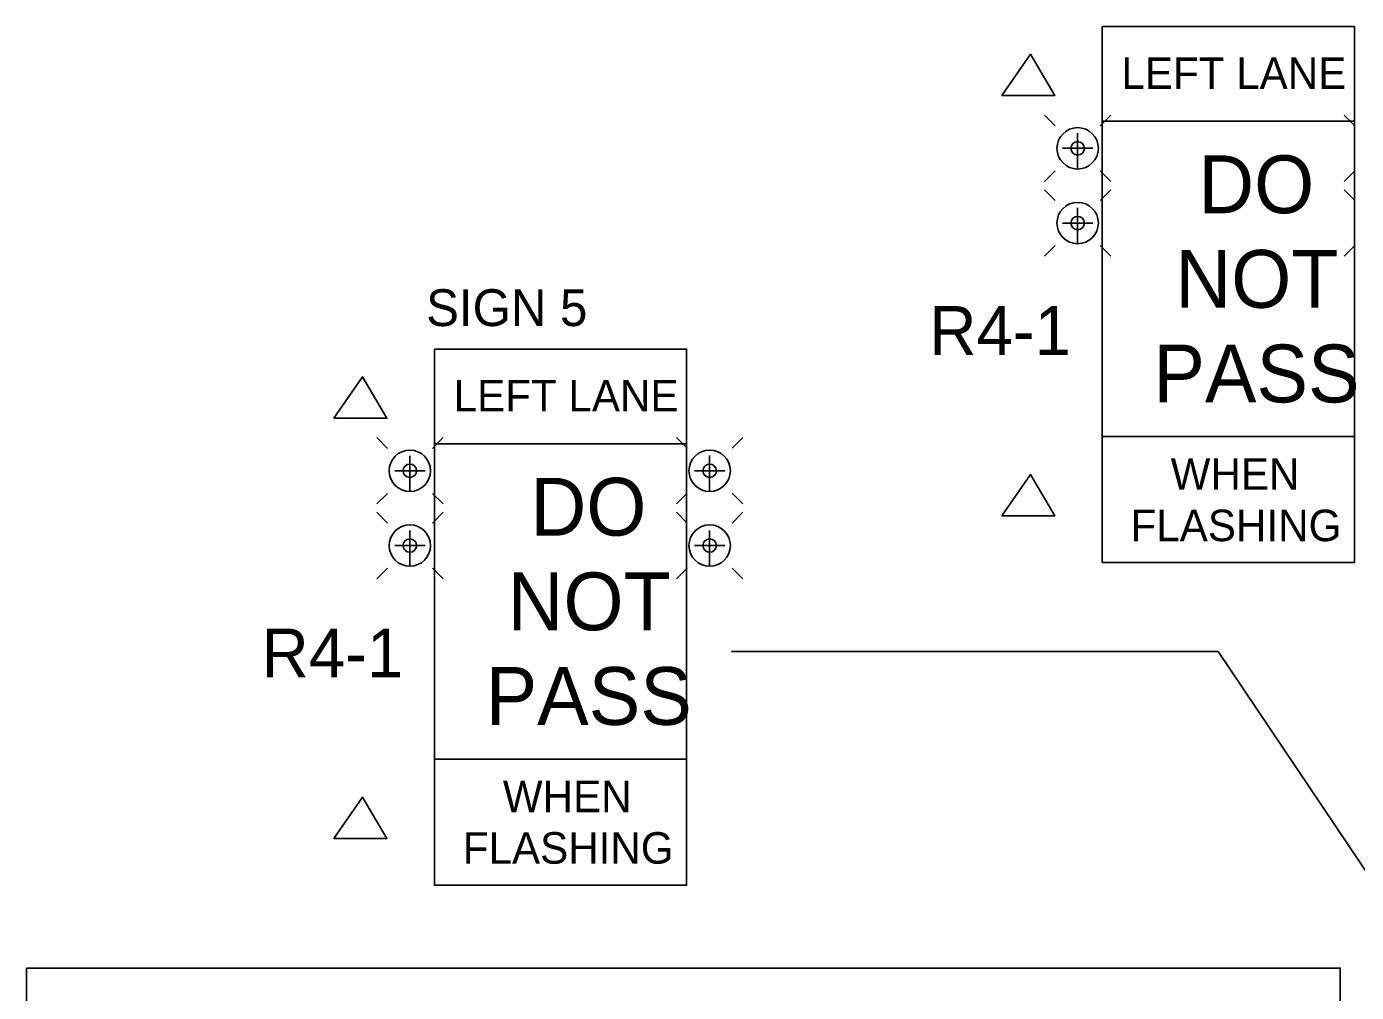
# Model space of a CAD drawing. Extents: x 15278 to 18126, y 1908 to 6555.
# Drawn here: x 16278.3 to 16480.8, y 2648.2 to 2795.2 of the extents above; entities that cross this region are included whole.
import ezdxf

# ---------------------------------------------------------------- set-up
doc = ezdxf.new("R2010")
doc.units = 0
doc.layers.add('TRAFFIC_SIGNS_PR', color=7, linetype='Continuous')
doc.layers.add('TYPICAL_TEXT_DIMEN_PR', color=7, linetype='Continuous')

msp = doc.modelspace()

# ---------------------------------------------------------------- linework, layer by layer
at = {"layer": 'TRAFFIC_SIGNS_PR'}
for p, q in [((16434.9, 2780.08), (16433.27, 2781.71)), ((16441.74, 2780.08), (16443.37, 2781.71)), ((16442.06, 2732.78), (16442.06, 2780.78)), ((16442.06, 2780.78), (16480.46, 2780.78)), ((16480.54, 2780.1), (16478.91, 2781.72)), ((16480.46, 2732.78), (16480.46, 2780.78)), ((16438.32, 2776.66), (16438.32, 2778.96)), ((16438.32, 2776.66), (16436.02, 2776.66)), ((16438.32, 2776.66), (16438.32, 2773.51)), ((16438.32, 2776.66), (16440.62, 2776.66)), ((16434.9, 2773.23), (16433.27, 2771.6)), ((16443.37, 2771.6), (16441.74, 2773.23)), ((16480.54, 2773.25), (16478.91, 2771.62)), ((16434.9, 2768.71), (16433.27, 2770.33)), ((16441.74, 2768.7), (16443.37, 2770.33)), ((16480.54, 2768.71), (16478.91, 2770.33)), ((16438.32, 2765.28), (16438.32, 2767.58)), ((16438.32, 2765.28), (16436.02, 2765.28)), ((16438.32, 2765.28), (16438.32, 2762.13)), ((16438.32, 2765.28), (16440.62, 2765.28)), ((16434.9, 2761.86), (16433.27, 2760.23)), ((16443.37, 2760.23), (16441.74, 2761.86)), ((16480.54, 2761.86), (16478.91, 2760.23)), ((16333.22, 2730.99), (16331.59, 2732.62)), ((16340.07, 2730.99), (16341.7, 2732.62)), ((16340.38, 2683.7), (16340.38, 2731.7)), ((16340.38, 2731.7), (16378.78, 2731.7)), ((16378.86, 2731.01), (16377.24, 2732.64)), ((16378.78, 2683.7), (16378.78, 2731.7)), ((16385.71, 2731.01), (16387.34, 2732.64)), ((16442.06, 2732.78), (16480.46, 2732.78)), ((16336.64, 2727.57), (16336.64, 2729.87)), ((16382.29, 2727.59), (16382.29, 2729.89)), ((16336.64, 2727.57), (16334.34, 2727.57)), ((16336.64, 2727.57), (16336.64, 2724.42)), ((16336.64, 2727.57), (16338.95, 2727.57)), ((16382.29, 2727.59), (16379.99, 2727.59)), ((16382.29, 2727.59), (16382.29, 2724.43)), ((16382.29, 2727.59), (16384.59, 2727.59)), ((16333.22, 2724.14), (16331.59, 2722.52)), ((16341.69, 2722.52), (16340.07, 2724.14)), ((16378.86, 2724.16), (16377.24, 2722.53)), ((16387.34, 2722.53), (16385.71, 2724.16)), ((16333.22, 2719.62), (16331.59, 2721.25)), ((16340.07, 2719.62), (16341.7, 2721.25)), ((16378.86, 2719.62), (16377.24, 2721.25)), ((16385.71, 2719.62), (16387.34, 2721.25)), ((16336.64, 2716.19), (16336.64, 2718.5)), ((16382.29, 2716.19), (16382.29, 2718.5)), ((16336.64, 2716.19), (16334.34, 2716.19)), ((16336.64, 2716.19), (16336.64, 2713.04)), ((16336.64, 2716.19), (16338.95, 2716.19)), ((16382.29, 2716.19), (16379.99, 2716.19)), ((16382.29, 2716.19), (16382.29, 2713.04)), ((16382.29, 2716.19), (16384.59, 2716.19)), ((16333.22, 2712.77), (16331.59, 2711.14)), ((16341.69, 2711.14), (16340.07, 2712.77)), ((16378.86, 2712.77), (16377.24, 2711.14)), ((16387.34, 2711.14), (16385.71, 2712.77)), ((16340.38, 2683.7), (16378.78, 2683.7))]:
    msp.add_line(p, q, dxfattribs=at)
msp.add_lwpolyline([(16278.29, 2651.89), (16478.29, 2651.89), (16478.29, 2547.89), (16278.29, 2547.89)], close=True, dxfattribs=at)
for centre, radius in [((16438.32, 2776.65), 3.15), ((16438.32, 2776.65), 1.02), ((16438.32, 2765.28), 3.15), ((16438.32, 2765.28), 1.02), ((16336.64, 2727.57), 3.15), ((16382.29, 2727.58), 3.15), ((16336.64, 2727.57), 1.02), ((16382.29, 2727.58), 1.02), ((16336.64, 2716.19), 3.15), ((16382.29, 2716.19), 3.15), ((16336.64, 2716.19), 1.02), ((16382.29, 2716.19), 1.02)]:
    msp.add_circle(centre, radius, dxfattribs=at)
at = {"layer": 'TYPICAL_TEXT_DIMEN_PR'}
for p, q in [((16459.72, 2700.07), (16385.59, 2700.07)), ((16494.38, 2648.48), (16459.72, 2700.07))]:
    msp.add_line(p, q, dxfattribs=at)
for points in [[(16442.06, 2795.18), (16480.46, 2795.18), (16480.46, 2780.78), (16442.06, 2780.78)], [(16426.76, 2784.67), (16431.12, 2790.97), (16434.83, 2784.67)], [(16340.38, 2746.09), (16378.78, 2746.09), (16378.78, 2731.7), (16340.38, 2731.7)], [(16325.08, 2735.58), (16329.45, 2741.88), (16333.15, 2735.58)], [(16442.06, 2732.78), (16480.46, 2732.78), (16480.46, 2713.59), (16442.06, 2713.59)], [(16426.76, 2720.7), (16431.12, 2727.01), (16434.83, 2720.7)], [(16340.38, 2683.7), (16378.78, 2683.7), (16378.78, 2664.5), (16340.38, 2664.5)], [(16325.08, 2671.62), (16329.45, 2677.92), (16333.15, 2671.62)]]:
    msp.add_lwpolyline(points, close=True, dxfattribs=at)

# ---------------------------------------------------------------- texts
at = {"layer": 'TRAFFIC_SIGNS_PR'}
for s, height, p in [('DO', 8.8, (16456.69, 2766.78)), ('NOT', 8.8, (16453.2, 2752.38)), ('R4-1', 7.44, (16415.74, 2745.2)), ('PASS', 8.8, (16449.85, 2737.98)), ('DO', 8.8, (16355.01, 2717.7)), ('NOT', 8.8, (16351.53, 2703.3)), ('R4-1', 7.44, (16314.07, 2696.12)), ('PASS', 8.8, (16348.18, 2688.9))]:
    msp.add_text(s, height=height, dxfattribs=at).set_placement(p)
at = {"layer": 'TYPICAL_TEXT_DIMEN_PR'}
for s, height, p in [('LEFT LANE', 4.8, (16444.98, 2785.69)), ('   SIGN 5   ', 5.6, (16332.88, 2749.6)), ('LEFT LANE', 4.8, (16343.31, 2736.6)), ('WHEN', 4.8, (16452.48, 2724.69)), ('FLASHING', 4.8, (16446.37, 2716.86)), ('WHEN', 4.8, (16350.8, 2675.61)), ('FLASHING', 4.8, (16344.7, 2667.77))]:
    msp.add_text(s, height=height, dxfattribs=at).set_placement(p)

doc.saveas('drawing.dxf')
